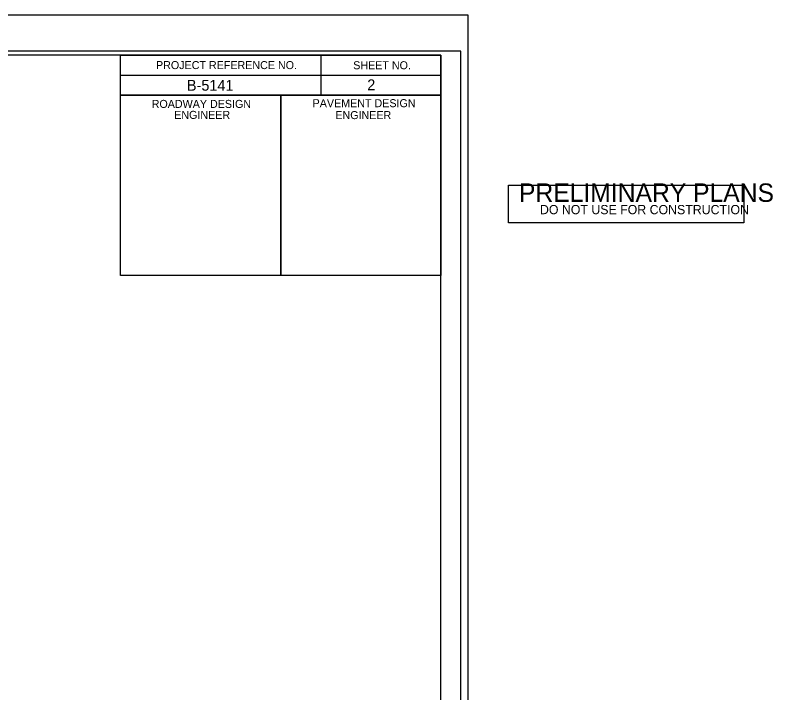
# Model space of a CAD drawing. Extents: x 9470 to 10081, y 10104 to 10463.
# Drawn here: x 10013 to 10079.2, y 10352.7 to 10412 of the extents above; entities that cross this region are included whole.
import ezdxf

# ---------------------------------------------------------------- set-up
doc = ezdxf.new("R2010")
doc.units = 0
for name, color, linetype in [('Sheet Cutting Line CELL', 7, 'Continuous'), ('Sheet Data Field CELL', 7, 'Continuous'), ('Sheet Plot Border Inside CELL', 7, 'Continuous'), ('Sheet Plot Border Outside CELL', 7, 'Continuous'), ('Sheet Sticker Preliminary CELL', 7, 'Continuous'), ('Sheet Typical CELL', 7, 'Continuous')]:
    doc.layers.add(name, color=color, linetype=linetype)

msp = doc.modelspace()

# ---------------------------------------------------------------- linework, layer by layer
at = {"layer": 'Sheet Cutting Line CELL'}
msp.add_line((10052.596, 10411.984), (9816.836, 10411.984), dxfattribs=at)
at = {"layer": 'Sheet Plot Border Inside CELL'}
msp.add_lwpolyline([(10051.966, 10408.841), (9818.656, 10408.841), (9818.656, 10261.127), (10051.966, 10261.127)], close=True, dxfattribs=at)
at = {"layer": 'Sheet Plot Border Outside CELL'}
msp.add_lwpolyline([(10052.596, 10411.984), (9816.836, 10411.984), (9816.836, 10257.984), (10052.596, 10257.984)], close=True, dxfattribs=at)
at = {"layer": 'Sheet Sticker Preliminary CELL'}
msp.add_lwpolyline([(10056.144, 10393.812), (10056.144, 10397.102), (10076.724, 10397.102), (10076.724, 10393.812)], close=True, dxfattribs=at)
at = {"layer": 'Sheet Typical CELL'}
for p, q in [((10039.716, 10408.477), (10039.716, 10404.977)), ((10022.209, 10406.727), (10050.216, 10406.727)), ((10036.216, 10404.977), (10036.216, 10389.234))]:
    msp.add_line(p, q, dxfattribs=at)
for points in [[(10050.216, 10408.484), (9840.216, 10408.484), (9840.216, 10261.484), (10050.216, 10261.484)], [(10022.209, 10408.484), (10050.216, 10408.484), (10050.216, 10404.977), (10022.209, 10404.977)], [(10022.209, 10404.977), (10036.216, 10404.977), (10036.216, 10389.227), (10022.209, 10389.227)], [(10036.216, 10404.977), (10050.216, 10404.977), (10050.216, 10389.227), (10036.216, 10389.227)]]:
    msp.add_lwpolyline(points, close=True, dxfattribs=at)

# ---------------------------------------------------------------- texts
at = {"layer": 'Sheet Data Field CELL'}
for s, p in [('B-5141   ', (10028.018, 10405.376)), (' 2 ', (10043.435, 10405.418))]:
    msp.add_text(s, height=0.945, dxfattribs=at).set_placement(p)
at = {"layer": 'Sheet Sticker Preliminary CELL'}
for s, height, p in [('PRELIMINARY PLANS', 1.6128, (10057.054, 10395.653)), ('DO NOT USE FOR CONSTRUCTION', 0.8064, (10058.888, 10394.575))]:
    msp.add_text(s, height=height, dxfattribs=at).set_placement(p)
at = {"layer": 'Sheet Typical CELL'}
for s, height, p in [('PROJECT REFERENCE NO.', 0.70001, (10025.317, 10407.266)), ('SHEET NO.', 0.7, (10042.558, 10407.252)), ('ROADWAY DESIGN', 0.70001, (10024.939, 10403.871)), ('PAVEMENT DESIGN', 0.70001, (10039.009, 10403.934)), ('ENGINEER', 0.7, (10026.906, 10402.912)), ('ENGINEER', 0.7, (10040.997, 10402.891))]:
    msp.add_text(s, height=height, dxfattribs=at).set_placement(p)

doc.saveas('drawing.dxf')
